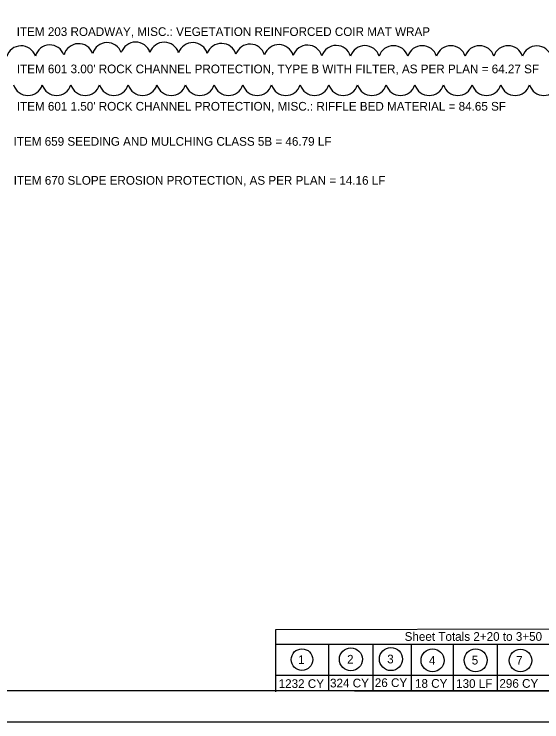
# Model space of a CAD drawing. Extents: x -34.1 to 34, y 0 to 22.
# Drawn here: x 21.29 to 29.76, y 0 to 11.37 of the extents above; entities that cross this region are included whole.
import ezdxf

# ---------------------------------------------------------------- set-up
doc = ezdxf.new("R2010")
doc.units = 0
for name, color, linetype in [('CS-ALGN-TEXT', 7, 'Continuous'), ('CS-ANNO', 7, 'Continuous'), ('CS-ANNO-MATC', 7, 'Continuous'), ('CS-ANNO-MATC-TEXT', 7, 'Continuous')]:
    doc.layers.add(name, color=color, linetype=linetype)

msp = doc.modelspace()

# ---------------------------------------------------------------- linework, layer by layer
at = {"layer": 'CS-ALGN-TEXT'}
for p, q in [((25.488, 1.483), (32, 1.5)), ((25.488, 0.483), (25.488, 1.483)), ((29.048, 0.501), (29.048, 1.251)), ((25.488, 1.25), (32, 1.25)), ((26.337, 0.5), (26.337, 1.25)), ((27.05, 0.5), (27.05, 1.25)), ((27.663, 0.5), (27.663, 1.25)), ((28.342, 0.5), (28.342, 1.25)), ((25.488, 0.75), (32, 0.75)), ((26.75, 0.5), (32, 0.5))]:
    msp.add_line(p, q, dxfattribs=at)
for centre, start, end in [((23.236, 10.677), 17.7394, 162.7394), ((23.695, 10.675), 16.8726, 161.8726), ((21.398, 10.617), 18.6837, 163.6837), ((21.859, 10.631), 19.8166, 164.8166), ((22.32, 10.652), 20.4064, 165.4064), ((22.778, 10.67), 19.0066, 164.0066), ((24.154, 10.668), 16.2316, 161.2316), ((24.614, 10.656), 15.9232, 160.9232), ((25.074, 10.645), 16.1989, 161.1989), ((25.535, 10.636), 16.4854, 161.4854), ((25.995, 10.628), 16.751, 161.751), ((26.456, 10.623), 16.998, 161.998), ((26.916, 10.62), 17.2284, 162.2284), ((27.376, 10.619), 17.4386, 162.4386), ((27.837, 10.619), 17.5, 162.5), ((28.297, 10.619), 17.5, 162.5), ((28.757, 10.619), 17.5, 162.5), ((29.217, 10.619), 17.5, 162.5), ((29.677, 10.616), 16.8833, 161.8833), ((21.507, 10.302), 197.5, 342.5), ((21.967, 10.302), 197.5, 342.5), ((22.427, 10.302), 197.5, 342.5), ((22.887, 10.302), 197.5, 342.5), ((23.348, 10.302), 197.5, 342.5), ((23.808, 10.302), 197.5, 342.5), ((24.268, 10.302), 197.5, 342.5), ((24.728, 10.302), 197.5, 342.5), ((25.188, 10.302), 197.5, 342.5), ((25.648, 10.302), 197.5, 342.5), ((26.109, 10.302), 197.5, 342.5), ((26.569, 10.302), 197.5, 342.5), ((27.029, 10.302), 197.5, 342.5), ((27.489, 10.302), 197.5, 342.5), ((27.949, 10.302), 197.5, 342.5), ((28.409, 10.302), 197.5, 342.5), ((28.87, 10.302), 197.5, 342.5), ((29.33, 10.302), 197.5, 342.5), ((29.79, 10.302), 197.5, 342.5)]:
    msp.add_arc(centre, 0.241, start, end, dxfattribs=at)
at = {"layer": 'CS-ANNO'}
msp.add_lwpolyline([(0, 0), (34, 0), (34, 22), (0, 22)], close=True, dxfattribs=at)
at = {"layer": 'CS-ANNO-MATC'}
msp.add_lwpolyline([(1.5, 21.5), (33.5, 21.5), (33.5, 0.5), (1.5, 0.5)], close=True, dxfattribs=at)
at = {"layer": 'CS-ANNO-MATC-TEXT'}
for centre, radius in [((25.907, 0.999), 0.174), ((26.692, 1.005), 0.184), ((27.335, 1.008), 0.185), ((28.003, 0.987), 0.184), ((28.695, 0.989), 0.184), ((29.415, 0.986), 0.181)]:
    msp.add_circle(centre, radius, dxfattribs=at)

# ---------------------------------------------------------------- texts
at = {"layer": 'CS-ALGN-TEXT'}
msp.add_text('Sheet Totals 2+20 to 3+50', height=0.14, dxfattribs=at).set_placement((27.555, 1.301))
at = {"layer": 'CS-ANNO-MATC-TEXT'}
for s, p in [('ITEM 203 ROADWAY, MISC.: VEGETATION REINFORCED COIR MAT WRAP', (21.327, 11.016)), ("ITEM 601 3.00' ROCK CHANNEL PROTECTION, TYPE B WITH FILTER, AS PER PLAN = 64.27 SF", (21.328, 10.417)), ("ITEM 601 1.50' ROCK CHANNEL PROTECTION, MISC.: RIFFLE BED MATERIAL = 84.65 SF", (21.328, 9.817)), ('ITEM 659 SEEDING AND MULCHING CLASS 5B = 46.79 LF', (21.277, 9.253)), ('ITEM 670 SLOPE EROSION PROTECTION, AS PER PLAN = 14.16 LF', (21.279, 8.627)), ('1', (25.846, 0.929)), ('2', (26.631, 0.935)), ('3', (27.275, 0.939)), ('4', (27.945, 0.917)), ('5', (28.632, 0.921)), ('7', (29.345, 0.917)), ('1232 CY', (25.532, 0.544)), ('324 CY', (26.357, 0.553)), ('26 CY', (27.076, 0.559)), ('18 CY', (27.721, 0.547)), ('130 LF', (28.381, 0.545)), ('296 CY', (29.076, 0.547))]:
    msp.add_text(s, height=0.14, dxfattribs=at).set_placement(p)

doc.saveas('drawing.dxf')
